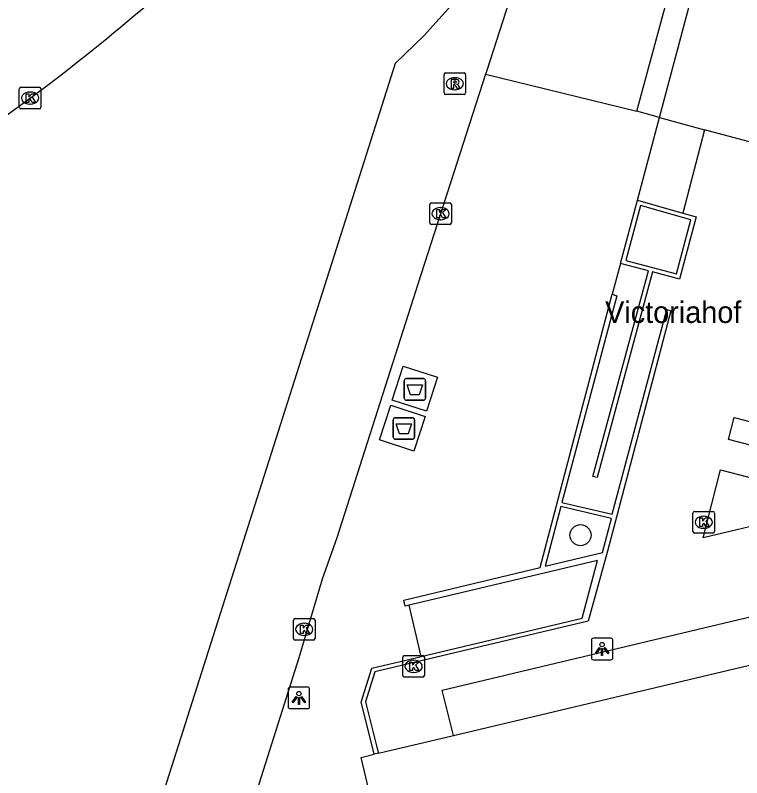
# Model space of a CAD drawing. Extents: x 160676 to 161153, y 383244 to 383713.
# Drawn here: x 160828.58 to 160862.26, y 383482.01 to 383517.37 of the extents above; entities that cross this region are included whole.
import ezdxf

# ---------------------------------------------------------------- set-up
doc = ezdxf.new("R2010")
doc.units = 0
for name, color, linetype in [('IMGEO_Afval_apart_plaats', 7, 'Continuous'), ('IMGEO_Boom', 7, 'Continuous'), ('IMGEO_Kolk', 7, 'Continuous'), ('IMGEO_Lichtpunt', 7, 'Continuous'), ('IMGEO_Muur', 7, 'Continuous'), ('IMGEO_Openbare_ruimte_label', 7, 'Continuous'), ('IMGEO_Pand', 7, 'Continuous'), ('IMGEO_Rijbaan_lokaal_gesloten', 7, 'Continuous'), ('IMGEO_Rioolput', 7, 'Continuous'), ('IMGEO_Voetpad_gesloten', 7, 'Continuous'), ('IMGEO_Voetpad_open', 7, 'Continuous')]:
    doc.layers.add(name, color=color, linetype=linetype)

msp = doc.modelspace()

# ---------------------------------------------------------------- linework, layer by layer
at = {"layer": 'IMGEO_Afval_apart_plaats'}
for p, q in [((160846.615, 383499.62), (160846.615, 383500.42)), ((160846.615, 383500.42), (160846.615, 383499.62)), ((160846.715, 383500.52), (160847.505, 383500.52)), ((160847.505, 383500.52), (160846.715, 383500.52)), ((160847.605, 383500.42), (160847.605, 383499.62)), ((160847.605, 383499.62), (160847.605, 383500.42)), ((160847.505, 383499.52), (160846.715, 383499.52)), ((160846.715, 383499.52), (160847.505, 383499.52)), ((160846.105, 383497.81), (160846.105, 383498.61)), ((160846.105, 383498.61), (160846.105, 383497.81)), ((160846.205, 383498.71), (160846.995, 383498.71)), ((160846.995, 383498.71), (160846.205, 383498.71)), ((160847.095, 383498.61), (160847.095, 383497.81)), ((160847.095, 383497.81), (160847.095, 383498.61)), ((160846.995, 383497.71), (160846.205, 383497.71)), ((160846.205, 383497.71), (160846.995, 383497.71))]:
    msp.add_line(p, q, dxfattribs=at)
for points in [[(160846.758, 383500.234), (160847.462, 383500.234), (160847.313, 383499.764), (160846.907, 383499.764), (160846.758, 383500.234)], [(160846.248, 383498.424), (160846.952, 383498.424), (160846.803, 383497.954), (160846.397, 383497.954), (160846.248, 383498.424)]]:
    msp.add_lwpolyline(points, dxfattribs=at)
for centre, start, end in [((160846.715, 383500.42), 90, 180), ((160846.715, 383500.42), 90, 180), ((160847.505, 383500.42), 0, 90), ((160847.505, 383500.42), 360, 90), ((160846.715, 383499.62), 180, 270), ((160846.715, 383499.62), 180, 270), ((160847.505, 383499.62), 270, 0), ((160847.505, 383499.62), 270, 0), ((160846.205, 383498.61), 90, 180), ((160846.205, 383498.61), 90, 180), ((160846.995, 383498.61), 0, 90), ((160846.995, 383498.61), 360, 90), ((160846.205, 383497.81), 180, 270), ((160846.205, 383497.81), 180, 270), ((160846.995, 383497.81), 270, 0), ((160846.995, 383497.81), 270, 0)]:
    msp.add_arc(centre, 0.1, start, end, dxfattribs=at)
at = {"layer": 'IMGEO_Boom'}
msp.add_circle((160854.786, 383493.261), 0.489, dxfattribs=at)
at = {"layer": 'IMGEO_Kolk'}
for p, q in [((160828.843, 383514.031), (160829.695, 383514.031)), ((160828.768, 383513.105), (160828.768, 383513.957)), ((160829.256, 383513.811), (160829.281, 383513.811)), ((160829.769, 383513.957), (160829.769, 383513.105)), ((160829.695, 383513.031), (160828.843, 383513.031)), ((160829.279, 383513.251), (160829.254, 383513.251)), ((160847.799, 383507.744), (160847.799, 383508.596)), ((160847.874, 383508.67), (160848.726, 383508.67)), ((160848.287, 383508.45), (160848.312, 383508.45)), ((160848.8, 383508.596), (160848.8, 383507.744)), ((160848.726, 383507.67), (160847.874, 383507.67)), ((160848.31, 383507.89), (160848.285, 383507.89)), ((160860.003, 383493.435), (160860.003, 383494.287)), ((160860.078, 383494.361), (160860.93, 383494.361)), ((160861.004, 383494.287), (160861.004, 383493.435)), ((160860.491, 383494.141), (160860.516, 383494.141)), ((160860.514, 383493.581), (160860.489, 383493.581)), ((160860.93, 383493.361), (160860.078, 383493.361)), ((160841.478, 383488.47), (160841.478, 383489.322)), ((160841.553, 383489.396), (160842.405, 383489.396)), ((160842.479, 383489.322), (160842.479, 383488.47)), ((160841.966, 383489.176), (160841.991, 383489.176)), ((160841.989, 383488.616), (160841.964, 383488.616)), ((160842.405, 383488.396), (160841.553, 383488.396)), ((160846.55, 383486.754), (160846.55, 383487.606)), ((160846.625, 383487.68), (160847.477, 383487.68)), ((160847.551, 383487.606), (160847.551, 383486.754)), ((160847.038, 383487.46), (160847.063, 383487.46)), ((160847.061, 383486.9), (160847.036, 383486.9)), ((160847.477, 383486.68), (160846.625, 383486.68))]:
    msp.add_line(p, q, dxfattribs=at)
for points in [[(160828.843, 383514.031), (160829.695, 383514.031)], [(160828.768, 383513.105), (160828.768, 383513.957)], [(160829.089, 383513.731), (160829.212, 383513.731), (160829.212, 383513.58), (160829.342, 383513.731), (160829.506, 383513.731), (160829.36, 383513.58), (160829.513, 383513.331), (160829.361, 383513.331), (160829.276, 383513.495), (160829.212, 383513.428), (160829.212, 383513.331), (160829.089, 383513.331), (160829.089, 383513.731)], [(160829.769, 383513.957), (160829.769, 383513.105)], [(160829.695, 383513.031), (160828.843, 383513.031)], [(160847.799, 383507.744), (160847.799, 383508.596)], [(160847.874, 383508.67), (160848.726, 383508.67)], [(160848.12, 383508.37), (160848.243, 383508.37), (160848.243, 383508.219), (160848.373, 383508.37), (160848.537, 383508.37), (160848.391, 383508.219), (160848.544, 383507.97), (160848.392, 383507.97), (160848.307, 383508.134), (160848.243, 383508.067), (160848.243, 383507.97), (160848.12, 383507.97), (160848.12, 383508.37)], [(160848.8, 383508.596), (160848.8, 383507.744)], [(160848.726, 383507.67), (160847.874, 383507.67)], [(160860.003, 383493.435), (160860.003, 383494.287)], [(160860.078, 383494.361), (160860.93, 383494.361)], [(160861.004, 383494.287), (160861.004, 383493.435)], [(160860.324, 383494.061), (160860.447, 383494.061), (160860.447, 383493.91), (160860.577, 383494.061), (160860.741, 383494.061), (160860.595, 383493.91), (160860.748, 383493.661), (160860.596, 383493.661), (160860.511, 383493.825), (160860.447, 383493.758), (160860.447, 383493.661), (160860.324, 383493.661), (160860.324, 383494.061)], [(160860.93, 383493.361), (160860.078, 383493.361)], [(160841.478, 383488.47), (160841.478, 383489.322)], [(160841.553, 383489.396), (160842.405, 383489.396)], [(160842.479, 383489.322), (160842.479, 383488.47)], [(160841.799, 383489.096), (160841.922, 383489.096), (160841.922, 383488.945), (160842.052, 383489.096), (160842.216, 383489.096), (160842.07, 383488.945), (160842.223, 383488.696), (160842.071, 383488.696), (160841.986, 383488.86), (160841.922, 383488.793), (160841.922, 383488.696), (160841.799, 383488.696), (160841.799, 383489.096)], [(160842.405, 383488.396), (160841.553, 383488.396)], [(160846.55, 383486.754), (160846.55, 383487.606)], [(160846.625, 383487.68), (160847.477, 383487.68)], [(160847.551, 383487.606), (160847.551, 383486.754)], [(160846.871, 383487.38), (160846.994, 383487.38), (160846.994, 383487.229), (160847.124, 383487.38), (160847.288, 383487.38), (160847.142, 383487.229), (160847.295, 383486.98), (160847.143, 383486.98), (160847.058, 383487.144), (160846.994, 383487.077), (160846.994, 383486.98), (160846.871, 383486.98), (160846.871, 383487.38)], [(160847.477, 383486.68), (160846.625, 383486.68)]]:
    msp.add_lwpolyline(points, dxfattribs=at)
for centre, start, end in [((160828.845, 383513.955), 91.552, 178.448), ((160828.845, 383513.955), 91.552, 178.448), ((160829.693, 383513.955), 1.552, 88.448), ((160829.693, 383513.955), 1.552, 88.448), ((160828.845, 383513.107), 181.552, 268.448), ((160828.845, 383513.107), 181.552, 268.448), ((160829.693, 383513.107), 271.552, 358.448), ((160829.693, 383513.107), 271.552, 358.448), ((160847.876, 383508.594), 91.552, 178.448), ((160847.876, 383508.594), 91.552, 178.448), ((160848.724, 383508.594), 1.552, 88.448), ((160848.724, 383508.594), 1.552, 88.448), ((160847.876, 383507.746), 181.552, 268.448), ((160847.876, 383507.746), 181.552, 268.448), ((160848.724, 383507.746), 271.552, 358.448), ((160848.724, 383507.746), 271.552, 358.448), ((160860.08, 383494.285), 91.552, 178.448), ((160860.08, 383494.285), 91.552, 178.448), ((160860.928, 383494.285), 1.552, 88.448), ((160860.928, 383494.285), 1.552, 88.448), ((160860.08, 383493.437), 181.552, 268.448), ((160860.08, 383493.437), 181.552, 268.448), ((160860.928, 383493.437), 271.552, 358.448), ((160860.928, 383493.437), 271.552, 358.448), ((160841.555, 383489.32), 91.552, 178.448), ((160841.555, 383489.32), 91.552, 178.448), ((160842.403, 383489.32), 1.552, 88.448), ((160842.403, 383489.32), 1.552, 88.448), ((160841.555, 383488.472), 181.552, 268.448), ((160841.555, 383488.472), 181.552, 268.448), ((160842.403, 383488.472), 271.552, 358.448), ((160842.403, 383488.472), 271.552, 358.448), ((160846.627, 383487.604), 91.552, 178.448), ((160846.627, 383487.604), 91.552, 178.448), ((160847.475, 383487.604), 1.552, 88.448), ((160847.475, 383487.604), 1.552, 88.448), ((160846.627, 383486.756), 181.552, 268.448), ((160846.627, 383486.756), 181.552, 268.448), ((160847.475, 383486.756), 271.552, 358.448), ((160847.475, 383486.756), 271.552, 358.448)]:
    msp.add_arc(centre, 0.0765, start, end, dxfattribs=at)
for centre, major_axis, ratio, start_param, end_param in [((160829.255, 383513.531), (-0.387, 0.002), 0.722429, 4.712389, 7.853982), ((160829.28, 383513.531), (-0.39, 0.002), 0.717154, 1.570796, 4.712389), ((160848.286, 383508.17), (-0.387, 0.002), 0.722429, 4.712389, 7.853982), ((160848.311, 383508.17), (-0.39, 0.002), 0.717154, 1.570796, 4.712389), ((160860.49, 383493.861), (-0.387, 0.002), 0.722429, 4.712389, 7.853982), ((160860.515, 383493.861), (-0.39, 0.002), 0.717154, 1.570796, 4.712389), ((160841.965, 383488.896), (-0.387, 0.002), 0.722429, 4.712389, 7.853982), ((160841.99, 383488.896), (-0.39, 0.002), 0.717154, 1.570796, 4.712389), ((160847.037, 383487.18), (-0.387, 0.002), 0.722429, 4.712389, 7.853982), ((160847.062, 383487.18), (-0.39, 0.002), 0.717154, 1.570796, 4.712389)]:
    msp.add_ellipse(centre, major_axis=major_axis, ratio=ratio, start_param=start_param, end_param=end_param, dxfattribs=at)
at = {"layer": 'IMGEO_Lichtpunt'}
for p, q in [((160855.291, 383488.389), (160855.291, 383487.582)), ((160855.291, 383488.389), (160855.291, 383487.582)), ((160856.193, 383488.484), (160855.385, 383488.484)), ((160856.193, 383488.484), (160855.385, 383488.484)), ((160856.287, 383487.582), (160856.287, 383488.389)), ((160856.287, 383487.582), (160856.287, 383488.389)), ((160855.385, 383487.488), (160856.193, 383487.488)), ((160855.385, 383487.488), (160856.193, 383487.488)), ((160841.231, 383486.121), (160841.231, 383485.314)), ((160841.231, 383486.121), (160841.231, 383485.314)), ((160842.133, 383486.216), (160841.325, 383486.216)), ((160842.133, 383486.216), (160841.325, 383486.216)), ((160842.227, 383485.314), (160842.227, 383486.121)), ((160842.227, 383485.314), (160842.227, 383486.121)), ((160841.325, 383485.22), (160842.133, 383485.22)), ((160841.325, 383485.22), (160842.133, 383485.22))]:
    msp.add_line(p, q, dxfattribs=at)
for points in [[(160855.665, 383488.053), (160855.704, 383488.025), (160855.516, 383487.763), (160855.478, 383487.79), (160855.665, 383488.053)], [(160855.767, 383488.005), (160855.814, 383488.005), (160855.814, 383487.683), (160855.767, 383487.683), (160855.767, 383488.005)], [(160855.877, 383488.025), (160855.915, 383488.052), (160856.102, 383487.79), (160856.063, 383487.762), (160855.877, 383488.025)], [(160841.605, 383485.785), (160841.644, 383485.757), (160841.456, 383485.495), (160841.418, 383485.522), (160841.605, 383485.785)], [(160841.707, 383485.737), (160841.754, 383485.737), (160841.754, 383485.415), (160841.707, 383485.415), (160841.707, 383485.737)], [(160841.817, 383485.757), (160841.855, 383485.784), (160842.042, 383485.522), (160842.003, 383485.494), (160841.817, 383485.757)]]:
    msp.add_lwpolyline(points, dxfattribs=at)
for centre in [(160855.79, 383488.187), (160841.73, 383485.919)]:
    msp.add_circle(centre, 0.0994, dxfattribs=at)
for centre, start, end in [((160855.385, 383488.389), 90, 180), ((160855.385, 383488.389), 90, 180), ((160856.193, 383488.389), 0, 90), ((160856.193, 383488.389), 0, 90), ((160855.385, 383487.582), 180, 270), ((160855.385, 383487.582), 180, 270), ((160856.193, 383487.582), 270, 0), ((160856.193, 383487.582), 270, 360), ((160841.325, 383486.121), 90, 180), ((160841.325, 383486.121), 90, 180), ((160842.133, 383486.121), 0, 90), ((160842.133, 383486.121), 0, 90), ((160841.325, 383485.314), 180, 270), ((160841.325, 383485.314), 180, 270), ((160842.133, 383485.314), 270, 0), ((160842.133, 383485.314), 270, 360)]:
    msp.add_arc(centre, 0.0946, start, end, dxfattribs=at)
at = {"layer": 'IMGEO_Muur'}
for points in [[(160856.642, 383505.862), (160857.425, 383508.79)], [(160857.425, 383508.79), (160859.527, 383508.197)], [(160859.901, 383507.884), (160857.566, 383508.542), (160856.887, 383506.004), (160859.243, 383505.385), (160859.901, 383507.884)], [(160859.527, 383508.197), (160860.145, 383508.023), (160859.383, 383505.129), (160858.12, 383505.47), (160855.558, 383495.937), (160855.367, 383495.985), (160857.943, 383505.52), (160856.642, 383505.862)], [(160856.259, 383504.432), (160856.466, 383504.365), (160853.926, 383494.777), (160856.26, 383494.24), (160858.791, 383503.725), (160858.982, 383503.672), (160856.035, 383492.516), (160855.136, 383489.273), (160845.258, 383486.926), (160844.819, 383485.533), (160845.349, 383483.436), (160845.426, 383483.152)], [(160846.845, 383490.02), (160846.655, 383489.975), (160846.59, 383490.251), (160852.923, 383491.77), (160856.259, 383504.432)], [(160853.144, 383491.823), (160855.814, 383492.463), (160856.231, 383494.042), (160853.871, 383494.585), (160853.144, 383491.823)], [(160847.399, 383487.636), (160854.868, 383489.411), (160855.577, 383492.09), (160846.845, 383490.02)], [(160845.219, 383483.103), (160845.139, 383483.432), (160844.621, 383485.519), (160845.111, 383487.092), (160847.212, 383487.592), (160847.399, 383487.636)]]:
    msp.add_lwpolyline(points, dxfattribs=at)
at = {"layer": 'IMGEO_Pand'}
for points in [[(160858.445, 383512.624), (160866.56, 383543.07), (160867.863, 383547.958), (160869.136, 383548.269), (160882.404, 383551.516)], [(160858.445, 383512.624), (160860.534, 383512.065)], [(160871.132, 383509.231), (160860.534, 383512.065)], [(160848.892, 383483.975), (160907.562, 383497.909)], [(160845.426, 383483.152), (160848.892, 383483.975)], [(160847.238, 383471.864), (160844.615, 383482.959), (160845.219, 383483.103)], [(160845.426, 383483.152), (160845.219, 383483.103)]]:
    msp.add_lwpolyline(points, dxfattribs=at)
at = {"layer": 'IMGEO_Rijbaan_lokaal_gesloten'}
for points in [[(160853.08, 383523.019), (160852.899, 383522.475), (160851.327, 383517.544), (160850.446, 383514.813), (160850.389, 383514.634)], [(160852.278, 383522.002), (160851.928, 383521.559), (160850.016, 383519.196), (160847.537, 383516.432), (160846.192, 383515.136), (160844.956, 383511.246), (160830.761, 383466.58), (160830.058, 383464.081)], [(160850.389, 383514.634), (160847.265, 383504.942), (160843.497, 383493.135), (160842.885, 383491.44), (160842.812, 383491.227), (160841.72, 383487.567), (160836.878, 383472.24), (160833.656, 383461.946)]]:
    msp.add_lwpolyline(points, dxfattribs=at)
at = {"layer": 'IMGEO_Rioolput'}
for p, q in [((160848.459, 383513.77), (160848.459, 383514.622)), ((160848.534, 383514.696), (160849.386, 383514.696)), ((160848.947, 383514.476), (160848.972, 383514.476)), ((160849.46, 383514.622), (160849.46, 383513.77)), ((160849.386, 383513.696), (160848.534, 383513.696)), ((160848.97, 383513.916), (160848.945, 383513.916))]:
    msp.add_line(p, q, dxfattribs=at)
for points in [[(160848.459, 383513.77), (160848.459, 383514.622)], [(160848.534, 383514.696), (160849.386, 383514.696)], [(160849.048, 383514.394), (160848.796, 383514.396), (160848.796, 383513.996)], [(160849.46, 383514.622), (160849.46, 383513.77)], [(160848.796, 383513.996), (160848.92, 383513.996), (160848.92, 383514.158), (160848.931, 383514.158)], [(160848.974, 383514.315), (160848.92, 383514.315), (160848.92, 383514.234)], [(160848.92, 383514.234), (160848.972, 383514.234)], [(160848.978, 383514.129), (160849.049, 383513.996), (160849.189, 383513.996), (160849.124, 383514.122)], [(160849.386, 383513.696), (160848.534, 383513.696)]]:
    msp.add_lwpolyline(points, dxfattribs=at)
for centre, radius, start, end in [((160848.536, 383514.62), 0.0765, 91.552, 178.448), ((160848.536, 383514.62), 0.0765, 91.552, 178.448), ((160849.047, 383514.284), 0.109, 350.3612, 89.416), ((160849.384, 383514.62), 0.0765, 1.552, 88.448), ((160849.384, 383514.62), 0.0765, 1.552, 88.448), ((160848.93, 383514.105), 0.0533, 26.0293, 88.6989), ((160848.956, 383514.423), 0.19, 274.7715, 282.9687), ((160848.98, 383514.219), 0.0964, 77.0061, 93.1865), ((160848.994, 383514.276), 0.0378, 276.6634, 79.6772), ((160849.045, 383514.284), 0.112, 277.5842, 350.9817), ((160849.029, 383514.069), 0.108, 29.5134, 73.7905), ((160848.536, 383513.772), 0.0765, 181.552, 268.448), ((160848.536, 383513.772), 0.0765, 181.552, 268.448), ((160849.384, 383513.772), 0.0765, 271.552, 358.448), ((160849.384, 383513.772), 0.0765, 271.552, 358.448)]:
    msp.add_arc(centre, radius, start, end, dxfattribs=at)
for centre, major_axis, ratio, start_param, end_param in [((160848.946, 383514.196), (-0.387, 0.002), 0.722429, 4.712389, 7.853982), ((160848.971, 383514.196), (-0.39, 0.002), 0.717154, 1.570796, 4.712389)]:
    msp.add_ellipse(centre, major_axis=major_axis, ratio=ratio, start_param=start_param, end_param=end_param, dxfattribs=at)
at = {"layer": 'IMGEO_Voetpad_gesloten'}
for points in [[(160846.062, 383499.515), (160846.572, 383501.101), (160848.157, 383500.591), (160847.647, 383499.005), (160846.062, 383499.515)], [(160845.463, 383497.687), (160845.991, 383499.286), (160847.589, 383498.759), (160847.061, 383497.16), (160845.463, 383497.687)]]:
    msp.add_lwpolyline(points, dxfattribs=at)
at = {"layer": 'IMGEO_Voetpad_open'}
for points in [[(160857.402, 383512.924), (160862.229, 383530.692), (160867.046, 383548.766)], [(160850.389, 383514.634), (160857.402, 383512.924)], [(160858.445, 383512.624), (160857.402, 383512.924)], [(160857.425, 383508.79), (160858.445, 383512.624)], [(160860.534, 383512.065), (160859.527, 383508.197)], [(160856.642, 383505.862), (160856.259, 383504.432)], [(160848.892, 383483.975), (160848.372, 383486.068), (160871.666, 383491.622), (160907.045, 383499.978), (160907.562, 383497.909)], [(160872.446, 383495.985), (160870.26, 383495.457), (160861.649, 383497.694), (160861.92, 383498.722), (160872.446, 383495.985)], [(160861.276, 383496.29), (160867.248, 383494.746), (160860.471, 383493.133), (160861.276, 383496.29)], [(160847.399, 383487.636), (160846.845, 383490.02)]]:
    msp.add_lwpolyline(points, dxfattribs=at)
for centre, radius, start, end in [((160761.862, 383603.196), 112.194, 307.97923, 314.6661), ((160757.151, 383610.954), 121.212, 293.7416, 307.47749)]:
    msp.add_arc(centre, radius, start, end, dxfattribs=at)

# ---------------------------------------------------------------- texts
at = {"layer": 'IMGEO_Openbare_ruimte_label'}
msp.add_text('Victoriahof', height=1, dxfattribs=at).set_placement((160855.929, 383503.103))

doc.saveas('drawing.dxf')
